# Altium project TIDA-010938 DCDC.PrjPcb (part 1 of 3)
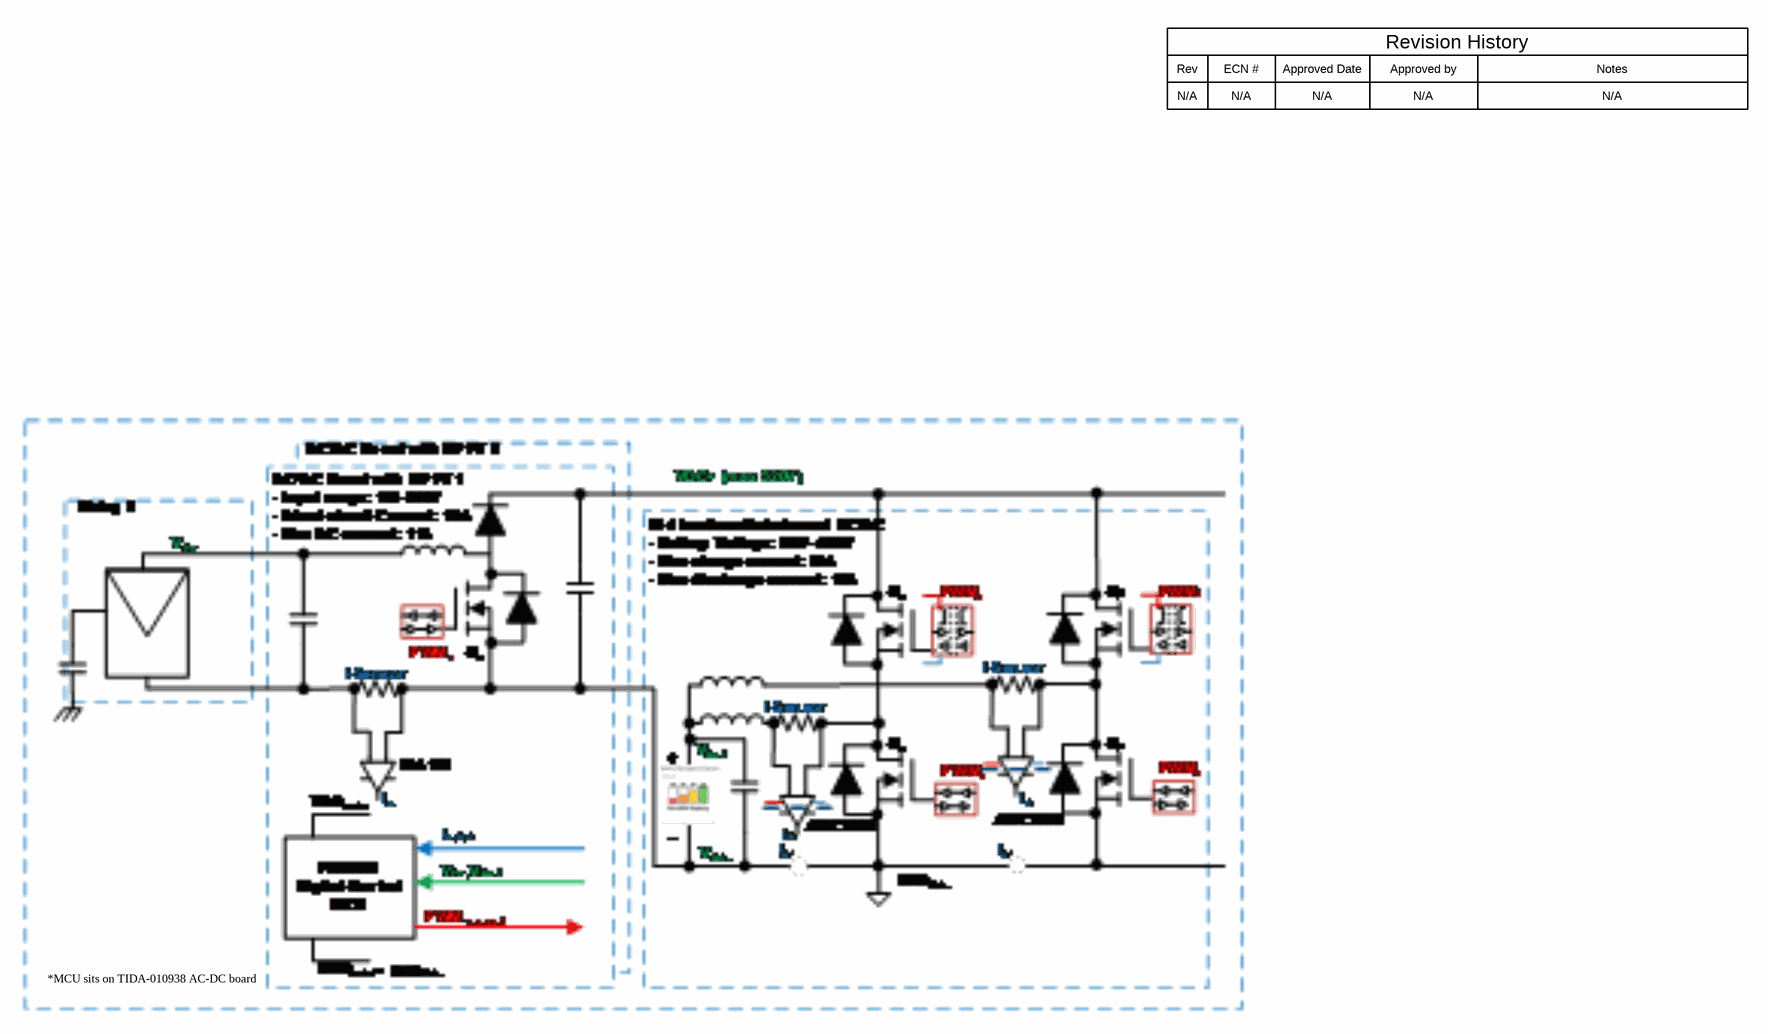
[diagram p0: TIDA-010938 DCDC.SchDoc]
CopyrightYear: 2023; PCB_Layout: Laure Chevallier; PCB_Rev: E1; PRJ_Customer: Public Release; PRJ_Engineer: Laure Chevallier; PRJ_Number: TIDA-010938 DC-DC; PRJ_Title: TIDA-010938 DC-DC; SCH_Rev: E1; TechSupport: http://www.ti.com/support; TID: A0497972
9 sheets, 437 parts. Net scope: flat (ports and power ports of the same name join across sheets).
Board file: TIDA-010938 DCDC.PcbDoc
Sheets:
  TIDA-010938 DCDC.SchDoc
    Designator = TIDA-010938 DCDC_Top.SchDoc
      Designator = TIDA-010938 DC-DC_Boost1.SchDoc
      Designator = TIDA-010938 DC-DC_Boost2.SchDoc
      Designator = TIDA-010938 bidirectional DC-DC_Interleaved1.SchDoc
      Designator = TIDA-010938 DC-DC_VoltageMeasurement.SchDoc
      Designator = TIDA-010938 DC-DC_Data conditionning.SchDoc
      Designator = TIDA-010938 bidirectional DC-DC_Interleaved2.SchDoc
      Designator = TIDA-010938 DCDC_Hardware.SchDoc

## Sheet TIDA-010938 DCDC.SchDoc
size 431 x 279 mm; Date: Not shown in title block; ApprovedBy: Not shown in title block; CheckedBy: Not shown in title block; Author: Not shown in title block; CompanyName: Not shown in title block; Engineer: Not shown in title block; Organization: Not shown in title block; Address1: Not shown in title block; Address2: Not shown in title block; Address3: Not shown in title block; Address4: Not shown in title block; DocumentNumber: 1; Revision: Use project parameter SCH_Rev; SheetNumber: 1; SheetTotal: 9; PageSetup: Record=PageOptions¦CenterHorizontal=True¦CenterVertical=True¦PrintScale=1.00¦XCorrection=1.00¦YCorrection=1.00¦PrintKind=0¦BorderSize=5000000¦LeftOffset=0¦BottomOffset=0¦Orientation=2¦PaperLength=1000¦PaperWidth=1000¦Scale=100¦PaperSource=15¦PrintQuality=600¦MediaType=1¦DitherType=10¦PaperKind=Letter¦PrintScaleMode=1

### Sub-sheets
Designator = TIDA-010938 DCDC_Top.SchDoc: no entries

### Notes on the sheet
- Rev
- N/A
- ECN #
- Approved Date
- Approved by
- Revision History
- Notes
- *MCU sits on TIDA-010938 AC-DC board

## Sheet TIDA-010938 DCDC_Top.SchDoc
size 431 x 279 mm; Date: Not shown in title block; ApprovedBy: Not shown in title block; CheckedBy: Not shown in title block; Author: Not shown in title block; CompanyName: Not shown in title block; Engineer: Not shown in title block; Organization: Not shown in title block; Address1: Not shown in title block; Address2: Not shown in title block; Address3: Not shown in title block; Address4: Not shown in title block; DocumentNumber: 1; Revision: Use project parameter SCH_Rev; SheetNumber: 2; SheetTotal: 9; PageSetup: Record=PageOptions¦CenterHorizontal=True¦CenterVertical=True¦PrintScale=1.00¦XCorrection=1.00¦YCorrection=1.00¦PrintKind=0¦BorderSize=5000000¦LeftOffset=0¦BottomOffset=0¦Orientation=2¦PaperLength=1000¦PaperWidth=1000¦Scale=100¦PaperSource=15¦PrintQuality=600¦MediaType=1¦DitherType=10¦PaperKind=Letter¦PrintScaleMode=1
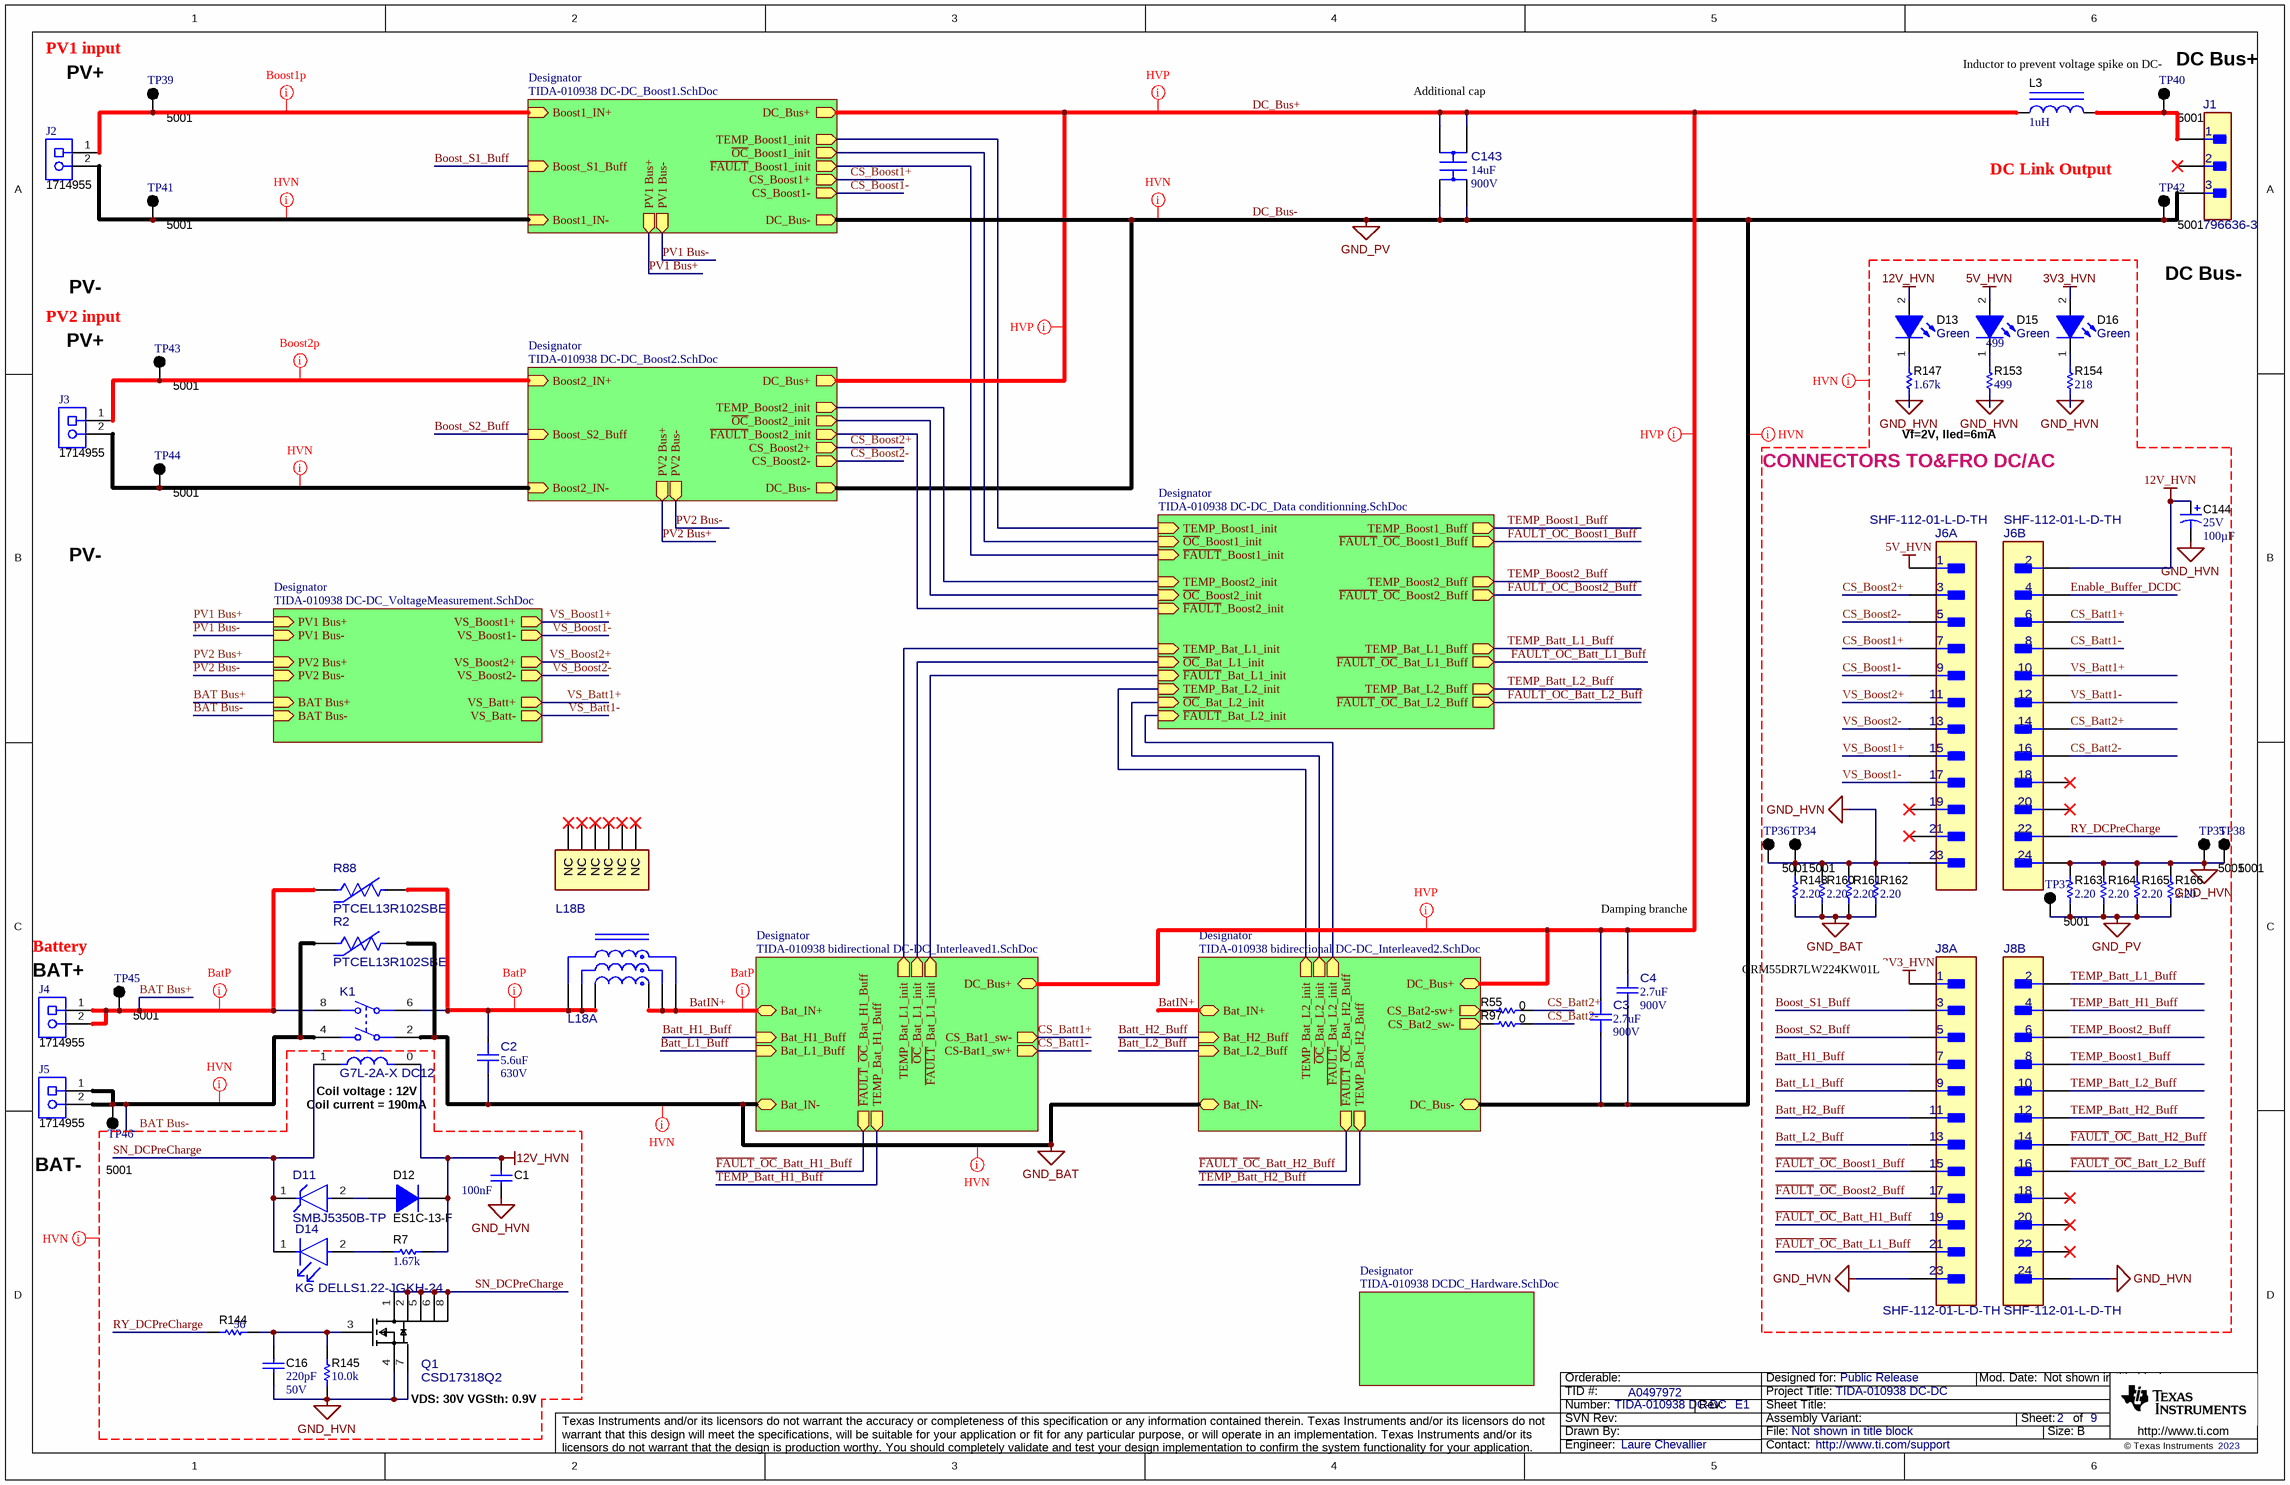
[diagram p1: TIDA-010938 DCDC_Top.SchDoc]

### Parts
C1  Cap_F: 100nF  [0603]  (hidden comment: GRM188R72A104KA35J)
C2  ValueDisplayed: 5.6uF  VDC_V: 630V  [FP-R533R456050P0M_RADIAL-MFG]  (hidden comment: R533R456050P0M)
C3  ValueDisplayed: 2.7uF  VDC_V: 900V  [FP-C4AKOBU4270A3YJ_RADIAL-MFG]  (hidden comment: C4AKOBU4270A3YJ)
C4  ValueDisplayed: 2.7uF  VDC_V: 900V  [FP-C4AKOBU4270A3YJ_RADIAL-MFG]  (hidden comment: C4AKOBU4270A3YJ)
C16  Cap_F: 220pF  VDC_V: 50V  [0603]  (hidden comment: GRM188R71H221KA01D)
C143  ValueDisplayed: 14uF  VDC_V: 900V  [FP-C4AKOBW5140A3JJ_RADIAL-MFG]  (hidden comment: C4AKOBW5140A3JJ)
C144  VDC_V: 25V  ValueDisplayed: 100µF  [UWT_630x770]  (hidden comment: UWT1E101MCL1GS)
D11  SMBJ5350B-TP  [FP-SMBJ5350B-TP_SMB-MFG]
D12  ES1C-13-F  [SMA]
D13  value Green  [WL-SMCW_GREEN]  (hidden comment: 150060VS75000)
D14  KG DELLS1.22-JGKH-24  [FP-KG DELLS1.22-JGKH-24_0603-MFG]
D15  value Green  [WL-SMCW_GREEN]  (hidden comment: 150060VS75000)
D16  value Green  [WL-SMCW_GREEN]  (hidden comment: 150060VS75000)
J1  796636-3  [FP-796636-3_HDR3-MFG]
J2  1714955  [Phoenix_1714955]
J3  1714955  [Phoenix_1714955]
J4  1714955  [Phoenix_1714955]
J5  1714955  [Phoenix_1714955]
J6  SHF-112-01-L-D-TH  [FP-SHF-112-01-L-D-TH_HDR24-MFG]  (parts A,B of 2)
J8  SHF-112-01-L-D-TH  [FP-SHF-112-01-L-D-TH_HDR24-MFG]  (parts A,B of 2)
K1  G7L-2A-X DC12  [FP-G7L-2A-X DC12_PTH_RELAY_52MM5_35MM5-MFG]
L3  ValueDisplayed: 1uH  [SRP1038A]  (hidden comment: SRP1038A-1R0M)
L18  B180986  [FP-B180986_PTH12-MFG]  (value not drawn)  (parts A,B of 2)
Q1  CSD17318Q2  [FP-CSD17318Q2_WSON6-MFG]
R2  PTCEL13R102SBE  [FP-PTCEL13R102SBE_RADIAL-MFG]
R7  ValueDisplayed: 1.67k  [0603]  (hidden comment: RT0603DRE071K67L)
R55  ValueDisplayed: 0  [0603]  (hidden comment: RCS06030000Z0EA)
R88  PTCEL13R102SBE  [FP-PTCEL13R102SBE_RADIAL-MFG]
R97  ValueDisplayed: 0  [0603]  (hidden comment: RCS06030000Z0EA)
R144  ValueDisplayed: 56  [0603]  (hidden comment: RG1608P-560-B-T5)
R145  ValueDisplayed: 10.0k  [0603]  (hidden comment: RG1608P-103-B-T5)
R147  ValueDisplayed: 1.67k  [0603]  (hidden comment: RT0603DRE071K67L)
R148  ValueDisplayed: 2.20  [1206]  (hidden comment: RC1206FR-072R2L)
R153  value 499  [0603]  (hidden comment: CRCW0603499RFKEAC)
R154  ValueDisplayed: 218  [0603]  (hidden comment: RT0603DRE07218RL)
R160  ValueDisplayed: 2.20  [1206]  (hidden comment: RC1206FR-072R2L)
R161  ValueDisplayed: 2.20  [1206]  (hidden comment: RC1206FR-072R2L)
R162  ValueDisplayed: 2.20  [1206]  (hidden comment: RC1206FR-072R2L)
R163  ValueDisplayed: 2.20  [1206]  (hidden comment: RC1206FR-072R2L)
R164  ValueDisplayed: 2.20  [1206]  (hidden comment: RC1206FR-072R2L)
R165  ValueDisplayed: 2.20  [1206]  (hidden comment: RC1206FR-072R2L)
R166  ValueDisplayed: 2.20  [1206]  (hidden comment: RC1206FR-072R2L)
TP34  5001  [Keystone5001]
TP35  5001  [Keystone5001]
TP36  5001  [Keystone5001]
TP37  5001  [Keystone5001]
TP38  5001  [Keystone5001]
TP39  5001  [Keystone5001]
TP40  5001  [Keystone5001]
TP41  5001  [Keystone5001]
TP42  5001  [Keystone5001]
TP43  5001  [Keystone5001]
TP44  5001  [Keystone5001]
TP45  5001  [Keystone5001]
TP46  5001  [Keystone5001]

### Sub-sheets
Designator = TIDA-010938 DC-DC_Boost1.SchDoc: Boost_S1_Buff (in), TEMP_Boost1_init (out), ~{FAULT}_Boost1_init (out), ~{OC}_Boost1_init (out), DC_Bus+ (out), DC_Bus- (out), Boost1_IN+ (in), Boost1_IN- (in), CS_Boost1+ (out), CS_Boost1- (out), PV1 Bus+ (out), PV1 Bus- (out)
Designator = TIDA-010938 DC-DC_Boost2.SchDoc: DC_Bus+ (out), DC_Bus- (out), Boost_S2_Buff (in), TEMP_Boost2_init (out), ~{FAULT}_Boost2_init (out), ~{OC}_Boost2_init (out), Boost2_IN+ (in), Boost2_IN- (in), CS_Boost2+ (out), CS_Boost2- (out), PV2 Bus+ (out), PV2 Bus- (out)
Designator = TIDA-010938 bidirectional DC-DC_Interleaved1.SchDoc: DC_Bus+ (bidir), Bat_IN+ (bidir), Bat_IN- (bidir), Bat_L1_Buff (in), Bat_H1_Buff (in), ~{FAULT}_Bat_L1_init (out), ~{FAULT}_~{OC}_Bat_H1_Buff (out), ~{OC}_Bat_L1_init (out), TEMP_Bat_H1_Buff (out), TEMP_Bat_L1_init (out), CS_Bat1_sw- (out), CS-Bat1_sw+ (out)
Designator = TIDA-010938 DC-DC_VoltageMeasurement.SchDoc: PV1 Bus+ (in), PV2 Bus+ (in), VS_Boost2+ (out), BAT Bus+ (in), BAT Bus- (in), VS_Batt+ (out), VS_Boost1+ (out), VS_Batt- (out), VS_Boost2- (out), VS_Boost1- (out), PV2 Bus- (in), PV1 Bus- (in)
Designator = TIDA-010938 DC-DC_Data conditionning.SchDoc: ~{FAULT}_Boost1_init (in), ~{OC}_Boost1_init (in), ~{FAULT}_Boost2_init (in), ~{OC}_Boost2_init (in), ~{FAULT}_Bat_L1_init (in), ~{OC}_Bat_L1_init (in), ~{FAULT}_Bat_L2_init (in), ~{OC}_Bat_L2_init (in), TEMP_Boost1_init (in), TEMP_Boost2_init (in), TEMP_Bat_L1_init (in), TEMP_Bat_L2_init (in), TEMP_Boost1_Buff (out), ~{FAULT}_~{OC}_Boost1_Buff (out), TEMP_Boost2_Buff (out), ~{FAULT}_~{OC}_Boost2_Buff (out), TEMP_Bat_L1_Buff (out), ~{FAULT}_~{OC}_Bat_L1_Buff (out), TEMP_Bat_L2_Buff (out), ~{FAULT}_~{OC}_Bat_L2_Buff (out)
Designator = TIDA-010938 bidirectional DC-DC_Interleaved2.SchDoc: DC_Bus+ (bidir), DC_Bus- (bidir), Bat_IN+ (bidir), Bat_IN- (bidir), Bat_L2_Buff (in), Bat_H2_Buff (in), TEMP_Bat_H2_Buff (out), ~{FAULT}_~{OC}_Bat_H2_Buff (out), ~{FAULT}_Bat_L2_init (out), ~{OC}_Bat_L2_init (out), TEMP_Bat_L2_init (out), CS_Bat2-sw+ (out), CS_Bat2_sw- (out)
Designator = TIDA-010938 DCDC_Hardware.SchDoc: no entries

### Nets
3V3_HVN: D16.2(A) J8.1
5V_HVN: D15.2(A) J6.1
12V_HVN: C1.1 C144.1(+) D12.1(K) D13.2(A) J6.2 K1.0 R7.1
DC_Bus-: C3.2 C4.2 C143.2 C143.4 J1.3 R163.1 R164.1 R165.1 R166.1 TP37.1 TP42.1 ; sheet Designator/DC_Bus-, sheet Designator/DC_Bus-, sheet Designator/DC_Bus-  [also labelled GND_PV]
GND_BAT: C2.1 K1.2 R2.2 R148.1 R160.1 R161.1 R162.1 ; sheet Designator/Bat_IN-, sheet Designator/Bat_IN-
GND_HVN: C1.2 C16.1 C144.2(-) J6.23 J6.24 J8.23 J8.24 Q1.4(S) Q1.7(S) R145.2 R147.1 R148.2 R153.1 R154.1 R160.2 R161.2 R162.2 R163.2 R164.2 R165.2 R166.2 TP34.1 TP35.1 TP36.1 TP38.1
BAT Bus+: J4.1 J4.2 K1.8 R88.1 TP45.1 ; sheet Designator/BAT Bus+
BAT Bus-: J5.1 J5.2 K1.4 R2.1 TP46.1 ; sheet Designator/BAT Bus-
BatIN+: L18.1 L18.2 L18.3 ; sheet Designator/Bat_IN+, sheet Designator/Bat_IN+
Batt_H1_Buff: J8.7 ; sheet Designator/Bat_H1_Buff
Batt_H2_Buff: J8.11 ; sheet Designator/Bat_H2_Buff
Batt_L1_Buff: J8.9 ; sheet Designator/Bat_L1_Buff
Batt_L2_Buff: J8.13 ; sheet Designator/Bat_L2_Buff
Boost_S1_Buff: J8.3 ; sheet Designator/Boost_S1_Buff
Boost_S2_Buff: J8.5 ; sheet Designator/Boost_S2_Buff
CS_Batt1+: J6.6 ; sheet Designator/CS_Bat1_sw-
CS_Batt1-: J6.8 ; sheet Designator/CS-Bat1_sw+
CS_Batt2+: J6.14 R55.2
CS_Batt2-: J6.16 R97.2
CS_Boost1+: J6.7 ; sheet Designator/CS_Boost1+
CS_Boost1-: J6.9 ; sheet Designator/CS_Boost1-
CS_Boost2+: J6.3 ; sheet Designator/CS_Boost2+
CS_Boost2-: J6.5 ; sheet Designator/CS_Boost2-
DC_Bus+: C3.1 C4.1 C143.1 C143.3 L3.1 ; sheet Designator/DC_Bus+, sheet Designator/DC_Bus+, sheet Designator/DC_Bus+, sheet Designator/DC_Bus+
Enable_Buffer_DCDC: J6.4
~{FAULT}_~{OC}_Batt_H1_Buff: J8.19 ; sheet Designator/~{FAULT}_~{OC}_Bat_H1_Buff
~{FAULT}_~{OC}_Batt_H2_Buff: J8.14 ; sheet Designator/~{FAULT}_~{OC}_Bat_H2_Buff
~{FAULT}_~{OC}_Batt_L1_Buff: J8.21 ; sheet Designator/~{FAULT}_~{OC}_Bat_L1_Buff
~{FAULT}_~{OC}_Batt_L2_Buff: J8.16 ; sheet Designator/~{FAULT}_~{OC}_Bat_L2_Buff
~{FAULT}_~{OC}_Boost1_Buff: J8.15 ; sheet Designator/~{FAULT}_~{OC}_Boost1_Buff
~{FAULT}_~{OC}_Boost2_Buff: J8.17 ; sheet Designator/~{FAULT}_~{OC}_Boost2_Buff
PV1 Bus+: sheet Designator/PV1 Bus+, sheet Designator/PV1 Bus+
PV1 Bus-: sheet Designator/PV1 Bus-, sheet Designator/PV1 Bus-
PV2 Bus+: sheet Designator/PV2 Bus+, sheet Designator/PV2 Bus+
PV2 Bus-: sheet Designator/PV2 Bus-, sheet Designator/PV2 Bus-
RY_DCPreCharge: J6.22 R144.1
SN_DCPreCharge: D11.1(CATHODE) D14.1(CATHODE) K1.1 Q1.1(D) Q1.2(D) Q1.5(D) Q1.6(D) Q1.8(D)
TEMP_Batt_H1_Buff: J8.4 ; sheet Designator/TEMP_Bat_H1_Buff
TEMP_Batt_H2_Buff: J8.12 ; sheet Designator/TEMP_Bat_H2_Buff
TEMP_Batt_L1_Buff: J8.2 ; sheet Designator/TEMP_Bat_L1_Buff
TEMP_Batt_L2_Buff: J8.10 ; sheet Designator/TEMP_Bat_L2_Buff
TEMP_Boost1_Buff: J8.8 ; sheet Designator/TEMP_Boost1_Buff
TEMP_Boost2_Buff: J8.6 ; sheet Designator/TEMP_Boost2_Buff
VS_Batt1+: J6.10 ; sheet Designator/VS_Batt+
VS_Batt1-: J6.12 ; sheet Designator/VS_Batt-
VS_Boost1+: J6.15 ; sheet Designator/VS_Boost1+
VS_Boost1-: J6.17 ; sheet Designator/VS_Boost1-
VS_Boost2+: J6.11 ; sheet Designator/VS_Boost2+
VS_Boost2-: J6.13 ; sheet Designator/VS_Boost2-
NetC2_2: C2.2 K1.6 L18.4 L18.5 L18.6 R88.2
NetC16_2: C16.2 Q1.3(G) R144.2 R145.1
NetD11_2: D11.2(ANODE) D12.2(A)
NetD13_1: D13.1(K) R147.2
NetD14_2: D14.2(ANODE) R7.2
NetD15_1: D15.1(K) R153.2
NetD16_1: D16.1(K) R154.2
NetJ1_1: J1.1 L3.2 TP40.1
NetJ2_1: J2.1 TP39.1 ; sheet Designator/Boost1_IN+
NetJ2_2: J2.2 TP41.1 ; sheet Designator/Boost1_IN-
NetJ3_1: J3.1 TP43.1 ; sheet Designator/Boost2_IN+
NetJ3_2: J3.2 TP44.1 ; sheet Designator/Boost2_IN-
NetR55_1: R55.1 ; sheet Designator/CS_Bat2-sw+
NetR97_1: R97.1 ; sheet Designator/CS_Bat2_sw-
(unnamed): sheet Designator/TEMP_Boost1_init, sheet Designator/TEMP_Boost1_init
(unnamed): sheet Designator/~{FAULT}_Boost1_init, sheet Designator/~{FAULT}_Boost1_init  [a separate net that carries the same name]
(unnamed): sheet Designator/~{OC}_Boost1_init, sheet Designator/~{OC}_Boost1_init  [a separate net that carries the same name]
(unnamed): sheet Designator/TEMP_Boost2_init, sheet Designator/TEMP_Boost2_init  [a separate net that carries the same name]
(unnamed): sheet Designator/~{FAULT}_Boost2_init, sheet Designator/~{FAULT}_Boost2_init  [a separate net that carries the same name]
(unnamed): sheet Designator/~{OC}_Boost2_init, sheet Designator/~{OC}_Boost2_init  [a separate net that carries the same name]
(unnamed): sheet Designator/~{FAULT}_Bat_L1_init, sheet Designator/~{FAULT}_Bat_L1_init  [a separate net that carries the same name]
(unnamed): sheet Designator/~{OC}_Bat_L1_init, sheet Designator/~{OC}_Bat_L1_init  [a separate net that carries the same name]
(unnamed): sheet Designator/TEMP_Bat_L1_init, sheet Designator/TEMP_Bat_L1_init  [a separate net that carries the same name]
(unnamed): sheet Designator/~{FAULT}_Bat_L2_init, sheet Designator/~{FAULT}_Bat_L2_init  [a separate net that carries the same name]
(unnamed): sheet Designator/~{OC}_Bat_L2_init, sheet Designator/~{OC}_Bat_L2_init  [a separate net that carries the same name]
(unnamed): sheet Designator/TEMP_Bat_L2_init, sheet Designator/TEMP_Bat_L2_init  [a separate net that carries the same name]

Not connected (* = marked no-connect by the designer): J1 2*; J6 18* 19* 20* 21*; J8 18* 20* 22*; L18 7(NC)* 8(NC)* 9(NC)* 10(NC)* 11(NC)* 12(NC)*

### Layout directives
net class HVN: 3V3_HVN, 5V_HVN, 12V_HVN, BAT Bus-, Batt_H1_Buff, Batt_H2_Buff, Batt_L1_Buff, Batt_L2_Buff, Boost_S1_Buff, Boost_S2_Buff, CS_Batt1+, CS_Batt1-, CS_Batt2+, CS_Batt2-, CS_Boost1+, CS_Boost1-, CS_Boost2+, CS_Boost2-, DC_Bus-, Enable_Buffer_DCDC, GND_BAT, GND_HVN, GND_PV, NetJ2_2, NetJ3_2, RY_DCPreCharge, SN_DCPreCharge, TEMP_Batt_H1_Buff, TEMP_Batt_H2_Buff, TEMP_Batt_L1_Buff, TEMP_Batt_L2_Buff, TEMP_Boost1_Buff, TEMP_Boost2_Buff, VS_Batt1+, VS_Batt1-, VS_Boost1+, VS_Boost1-, VS_Boost2+, VS_Boost2-, ~{FAULT}_~{OC}_Batt_H1_Buff, ~{FAULT}_~{OC}_Batt_H2_Buff, ~{FAULT}_~{OC}_Batt_L1_Buff, ~{FAULT}_~{OC}_Batt_L2_Buff, ~{FAULT}_~{OC}_Boost1_Buff, ~{FAULT}_~{OC}_Boost2_Buff
net class Boost1p: NetJ2_1
net class Boost2p: NetJ3_1
net class HVP: DC_Bus+
net class BatP: BAT Bus+, BatIN+, NetC2_2

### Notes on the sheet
- (near TP39) PV1 input
- PV+
- Additional cap
- Inductor to prevent voltage spike on DC-
- (near TP40) DC Bus+
- DC Link Output
- PV-
- DC Bus-
- PV2 input
- Vf=2V, Iled=6mA
- CONNECTORS TO&FRO DC/AC
- Battery
- BAT+
- Damping branche
- GRM55DR7LW224KW01L
- (near K1) Coil voltage : 12V
- (near K1) Coil current = 190mA
- BAT-
- (near Q1) VDS: 30V VGSth: 0.9V

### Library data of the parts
C1 = CMP-0007470-5: CAP, CERM, 0.1 uF, 100 V, +/- 10%, X7R, 0603; Manufacturer: MuRata; TaMin_C: -55°C; Polarized: N; SizeAreaWB_mm2: 4.68; Value1: Unknown; U/M: EA; Value: 0.1uF; TaMax_C: 125°C; SizeZ_mm: 1; SizeX_mm: 1.6; SizeY_mm: 0.8; Value2: 100V; SizeArea_mm2: 1.28; AEC Category: Q200
C2 = CMP-0045188-1: 5.6 µF Film Capacitor 310V 630V Polypropylene (PP), Metallized Radial; Manufacturer: KEMET; AEC Grade: Grade 3; AEC Qualified: Yes; Cap_F: 5.6µF; SizeZ_mm: 30.3mm; Tolerance_%: 20%; VAC_X: X2; Value: 5.6µF
C3 C4 = CMP-0045062-1: 2.7 µF Film Capacitor 900V Polypropylene (PP), Metallized Radial; Manufacturer: Kemet; AEC Grade: Grade 1; AEC Qualified: Yes; Cap_F: 2.7µF; SizeZ_mm: 28.7mm; Tolerance_%: 5%; Value: 2.7µF
C16 = CMP-0007442-5: CAP, CERM, 220 pF, 50 V, +/- 10%, X7R, 0603; Manufacturer: MuRata; TaMin_C: -55°C; Polarized: N; SizeAreaWB_mm2: 4.68; Value1: Unknown; U/M: EA; Value: 220pF; TaMax_C: 125°C; SizeZ_mm: 1; SizeX_mm: 1.6; SizeY_mm: 0.8; SizeArea_mm2: 1.28; AEC Category: Q200
C143 = CMP-0045770-1: 14 µF Film Capacitor 900V Polypropylene (PP), Metallized Radial - 4 Leads; Manufacturer: Kemet; AEC Grade: Grade 1; AEC Qualified: Yes; Cap_F: 14µF; SizeZ_mm: 38mm; Tolerance_%: 5%; Standoff Height: 0.5mm; Value: 14µF
C144 = CMP-0081462-1: CAP, AL, 100 µF, 25 V, +/- 20%, SMD; Manufacturer: Nichicon; TaMin_C: -55°C; Polarized: Y; SizeAreaWB_mm2: 77.4; U/M: EA; Value: 100uF; TaMax_C: 105°C; SizeZ_mm: 8; SizeX_mm: 7; SizeY_mm: 6.6; Cap_Case: 6.3x7.7mm; SizeArea_mm2: 46.2; CompType: Capacitor; AEC Qualified: N; IRMS_A: 91mA; AEC Category: Q200
D11 = CMP-0097215-1: Zener Diode 13 V 5 W ±5% Surface Mount DO-214AA (SMB); Manufacturer: MCC; Power_W: 5W; Standoff Height: 0.05mm; Vr_V: 9.9V; SizeZ_mm: 2.62mm; Zener Impedance: 2.5Ω; AEC Qualified: No; Max Reverse Leakage Current: 1uA; Vz_V: 13V; Vf_V: 13.65V; TJmax_C: 150°C
D12 = CMP-0029023-2: Diode, Superfast Rectifier, 150 V, 1 A, SMA; Manufacturer: Diodes Inc.; TJmax_C: 150°C; Vr_V: 150V; Value2: 0.92V; SizeX_mm: 5.59; Green_REACh: Incomplete; SizeAreaWB_mm2: 37.3428; Value: 150V; Vf_V: 920mV; Green_Lifecycle: Not Set; Value1: 1A; SizeZ_mm: 2.87; SizeArea_mm2: 16.3228; SizeY_mm: 2.92; AEC Category: Q101; RJC_CperW: 25
D13 D15 D16 = CMP-0002894-2: LED, Green, SMD; Manufacturer: Wurth Elektronik; Type: AlInGaP; Value2: 2V; Io_A: 20mA; Value1: W
D14 = CMP-0093310-1: Standard LEDs - SMD Green TOPLED E 1608; Manufacturer: Osram Opto; AEC Grade: Grade 2; LambdaP: 572nm; SizeZ_mm: 0.7mm; LuminousFlux_PhiV: 0.016-0.0295lm; Luminous Intensity: 4.5-9.7mcd; LambdaD: 570nm; Tjmax_C: 125°C; Angle: 120°; Led Orientation: Top View; Forward Current: 2mA; Vf_V: 1.8V; AEC Qualified: Yes; Vr_V: 12V
J1 = CMP-0094328-1: 3 Position Terminal Block Header, Male Pins, Shrouded (4 Side) 0.200" (5.08mm) Vertical - Through Hole; Manufacturer: TE Connectivity; Current_A: 15A; Row_Count: 1; AEC Qualified: No; Voltage_V: 300V; SizeZ_mm: 12.25mm; Min Wire Gauge: 30; ContactFinish: Tin; Max Wire Gauge: 12
J2-J5 = CMP-0055505-1: Terminal Block, 2x1, 6.35mm, Green, TH; Manufacturer: Phoenix Contact; CNHeader: FALSE; Shrouded: Y; Gender: Female; Row_Count: 1; Pitch_mm: 6.35; CT: TRUE
J6 J8 = CMP-0003796-1: Conn Shrouded Header (4 Sides) HDR 24 POS 1.27mm Solder ST Top Entry Thru-Hole Tube; Manufacturer: Samtec; ContactFinish: Gold,Nickel; Row_Count: 2; AEC Qualified: No; Conn Gender: Male; Conn Orientation: Straight; SizeZ_mm: 5.46mm; Standoff Height: 0.38mm
K1 = CMP-0093885-1: General Purpose Relay DPST-NO (2 Form A) 12VDC Coil Through Hole; Manufacturer: Omron; SizeZ_mm: 41mm; Coil Power_W: 2.3W; TaMax_C: +85°C; Switching Current: 30A; TaMin_C: -40°C; Coil Voltage_VDC: 12V; Coil Current_A: 191.7mA; Coil Resistance: 63Ω; Coil Type: Non-Latching; AEC Qualified: No
L3 = CMP-0056795-1: Inductor, Shielded, Powdered Iron, 1 uH, 18 A, 0.003 ohm, AEC-Q200 Grade 1, SMD; Manufacturer: Bourns; Isat: 36A @ 20% inductance drop; Irms: 18A @ 40C rise; Green_Lifecycle: Active; SizeAreaWB_mm2: 156; DCR_ohm: 3m; Green_REACh: Passed; Value: 1uH; Imax_A: 18A; SizeZ_mm: 4; SizeX_mm: 11; SizeY_mm: 10; SizeArea_mm2: 110; Ind_H: 1µH; AEC Qualified: Y; AEC Grade: 1; AEC Category: Q200
L18 = CMP-0047896-1: Inductor 22μH 4.7mΩ; Manufacturer: Bourns; AEC Qualified: No; DCR_ohm: 4.7m; SizeZ_mm: 40mm; Value: 22uH; Test Frequency: 100kHz
Q1 = CMP-0076725-1: 30-V N-Channel NexFET™ Power MOSFET; Manufacturer: Texas Instruments; VdsMax_V: 30V; SizeZ_mm: 0.8mm; ChMode: False; QgTyp_nC: 6nC @ 4.5V; Rdson45_ohm: 0.0139; Vgs_V: 10V; AEC Qualified: No; IdsMax_A: 10A
R2 R88 = CMP-0043438-1: PTCEL Series 850 V 1 kOhm ±30 % Radial Inrush Current Limiter PTC Thermistor; Manufacturer: Vishay; SizeZ_mm: 17mm; Value: 1000Ω; AEC Grade: Grade 2; AEC Qualified: Yes; Hold Current: 30mA; Max Current: 40A; Standoff Height: 2mm; Tolerance_%: 30%; VDC_V: 850V
R7 R147 = CMP-0024836-3: RES, 1.67 k, 0.5%, 0.1 W, 0603; Manufacturer: Yageo America; Power_W: 100mW; TempCo: 50 ppm/C; Value_Code: 1k67; U/M: EA; Value: 1.67k; EIA_Code: E192; SizeX_mm: 1.6; SizeY_mm: 0.8; SizeZ_mm: 1; Value2: 0.1W; SizeArea_mm2: 1.28; VDC_V: 75V; AEC Category: Q200
R55 R97 = CMP-0081973-1: RES, 0, 0%, 0.25 W, AEC-Q200 Grade 0, 0603; Manufacturer: Vishay-Dale; SizeAreaWB_mm2: 4.68; SizeArea_mm2: 1.28; AEC Qualified: Y; AEC Category: Q200; Value: 0; SizeZ_mm: 1; SizeY_mm: 0.8; Power_W: 250mW; Value2: 0.25W; SizeX_mm: 1.6
R144 = CMP-0023572-3: RES, 56, 0.1%, 0.1 W, 0603; Manufacturer: Susumu Co Ltd; Power_W: 100mW; TempCo: 25 ppm/C; Value_Code: 56R0; U/M: EA; Value: 56; SizeX_mm: 1.6; SizeY_mm: 0.8; SizeZ_mm: 1; Value2: 0.1W; SizeArea_mm2: 1.28; VDC_V: 75V; AEC Category: Q200
R145 = CMP-0023404-1: RES, 10.0 k, 0.1%, 0.1 W, 0603; Manufacturer: Susumu Co Ltd; Power_W: 100mW; TempCo: 25 ppm/C; Value_Code: 10k0; U/M: EA; Value: 10.0k; EIA_Code: E192; Res_ohm: 10k; SizeX_mm: 1.6; SizeY_mm: 0.8; SizeZ_mm: 1; Value2: 0.1W; SizeArea_mm2: 1.28; VDC_V: 75V; AEC Category: Q200
R148 R160-R166 = CMP-0018170-2: RES, 2.20, 1%, 0.25 W, 1206; Manufacturer: Yageo America; Power_W: 250mW; TempCo: 200 ppm/C; Value_Code: 2R20; U/M: EA; Value: 2.20; Res_ohm: 2.2; SizeX_mm: 3.2; SizeY_mm: 1.6; SizeZ_mm: 1.35; Value2: 0.25W; SizeArea_mm2: 5.12; VDC_V: 200V; AEC Category: Q200
R153 = CMP-0082532-1: RES, 499, 1%, 0.1 W, 0603; Manufacturer: Vishay-Dale; Power_W: 100mW; TempCo: 100 ppm/C; SizeAreaWB_mm2: 4.68; Value_Code: 499R; EIA_Code: E96; SizeX_mm: 1.6; SizeY_mm: 0.8; SizeZ_mm: 1; Value2: 0.1W; SizeArea_mm2: 1.28; AEC Qualified: N; VDC_V: 75V; AEC Category: Q200
R154 = CMP-0024934-2: RES, 218, 0.5%, 0.1 W, 0603; Manufacturer: Yageo America; Power_W: 100mW; TempCo: 50 ppm/C; Value_Code: 218R; U/M: EA; Value: 218; EIA_Code: E192; SizeX_mm: 1.6; SizeY_mm: 0.8; SizeZ_mm: 1; Value2: 0.1W; SizeArea_mm2: 1.28; VDC_V: 75V; AEC Category: Q200
TP34-TP46 = CMP-0055138-2: Test Point, Miniature, Black, TH; Manufacturer: Keystone Electronics; ContactFinish: Silver; CNHeader: FALSE; Green_Lifecycle: Active; Green_REACh: Passed; CT: TRUE

## Sheet TIDA-010938 DC-DC_Boost1.SchDoc
size 431 x 279 mm; Date: Not shown in title block; ApprovedBy: Not shown in title block; CheckedBy: Not shown in title block; Author: Not shown in title block; CompanyName: Not shown in title block; Engineer: Not shown in title block; Organization: Not shown in title block; Address1: Not shown in title block; Address2: Not shown in title block; Address3: Not shown in title block; Address4: Not shown in title block; DocumentNumber: 1; Revision: Use project parameter SCH_Rev; SheetNumber: 3; SheetTotal: 9; PageSetup: Record=PageOptions¦CenterHorizontal=True¦CenterVertical=True¦PrintScale=1.00¦XCorrection=1.00¦YCorrection=1.00¦PrintKind=0¦BorderSize=5000000¦LeftOffset=0¦BottomOffset=0¦Orientation=2¦PaperLength=1000¦PaperWidth=1000¦Scale=100¦PaperSource=15¦PrintQuality=600¦MediaType=1¦DitherType=10¦PaperKind=Letter¦PrintScaleMode=1
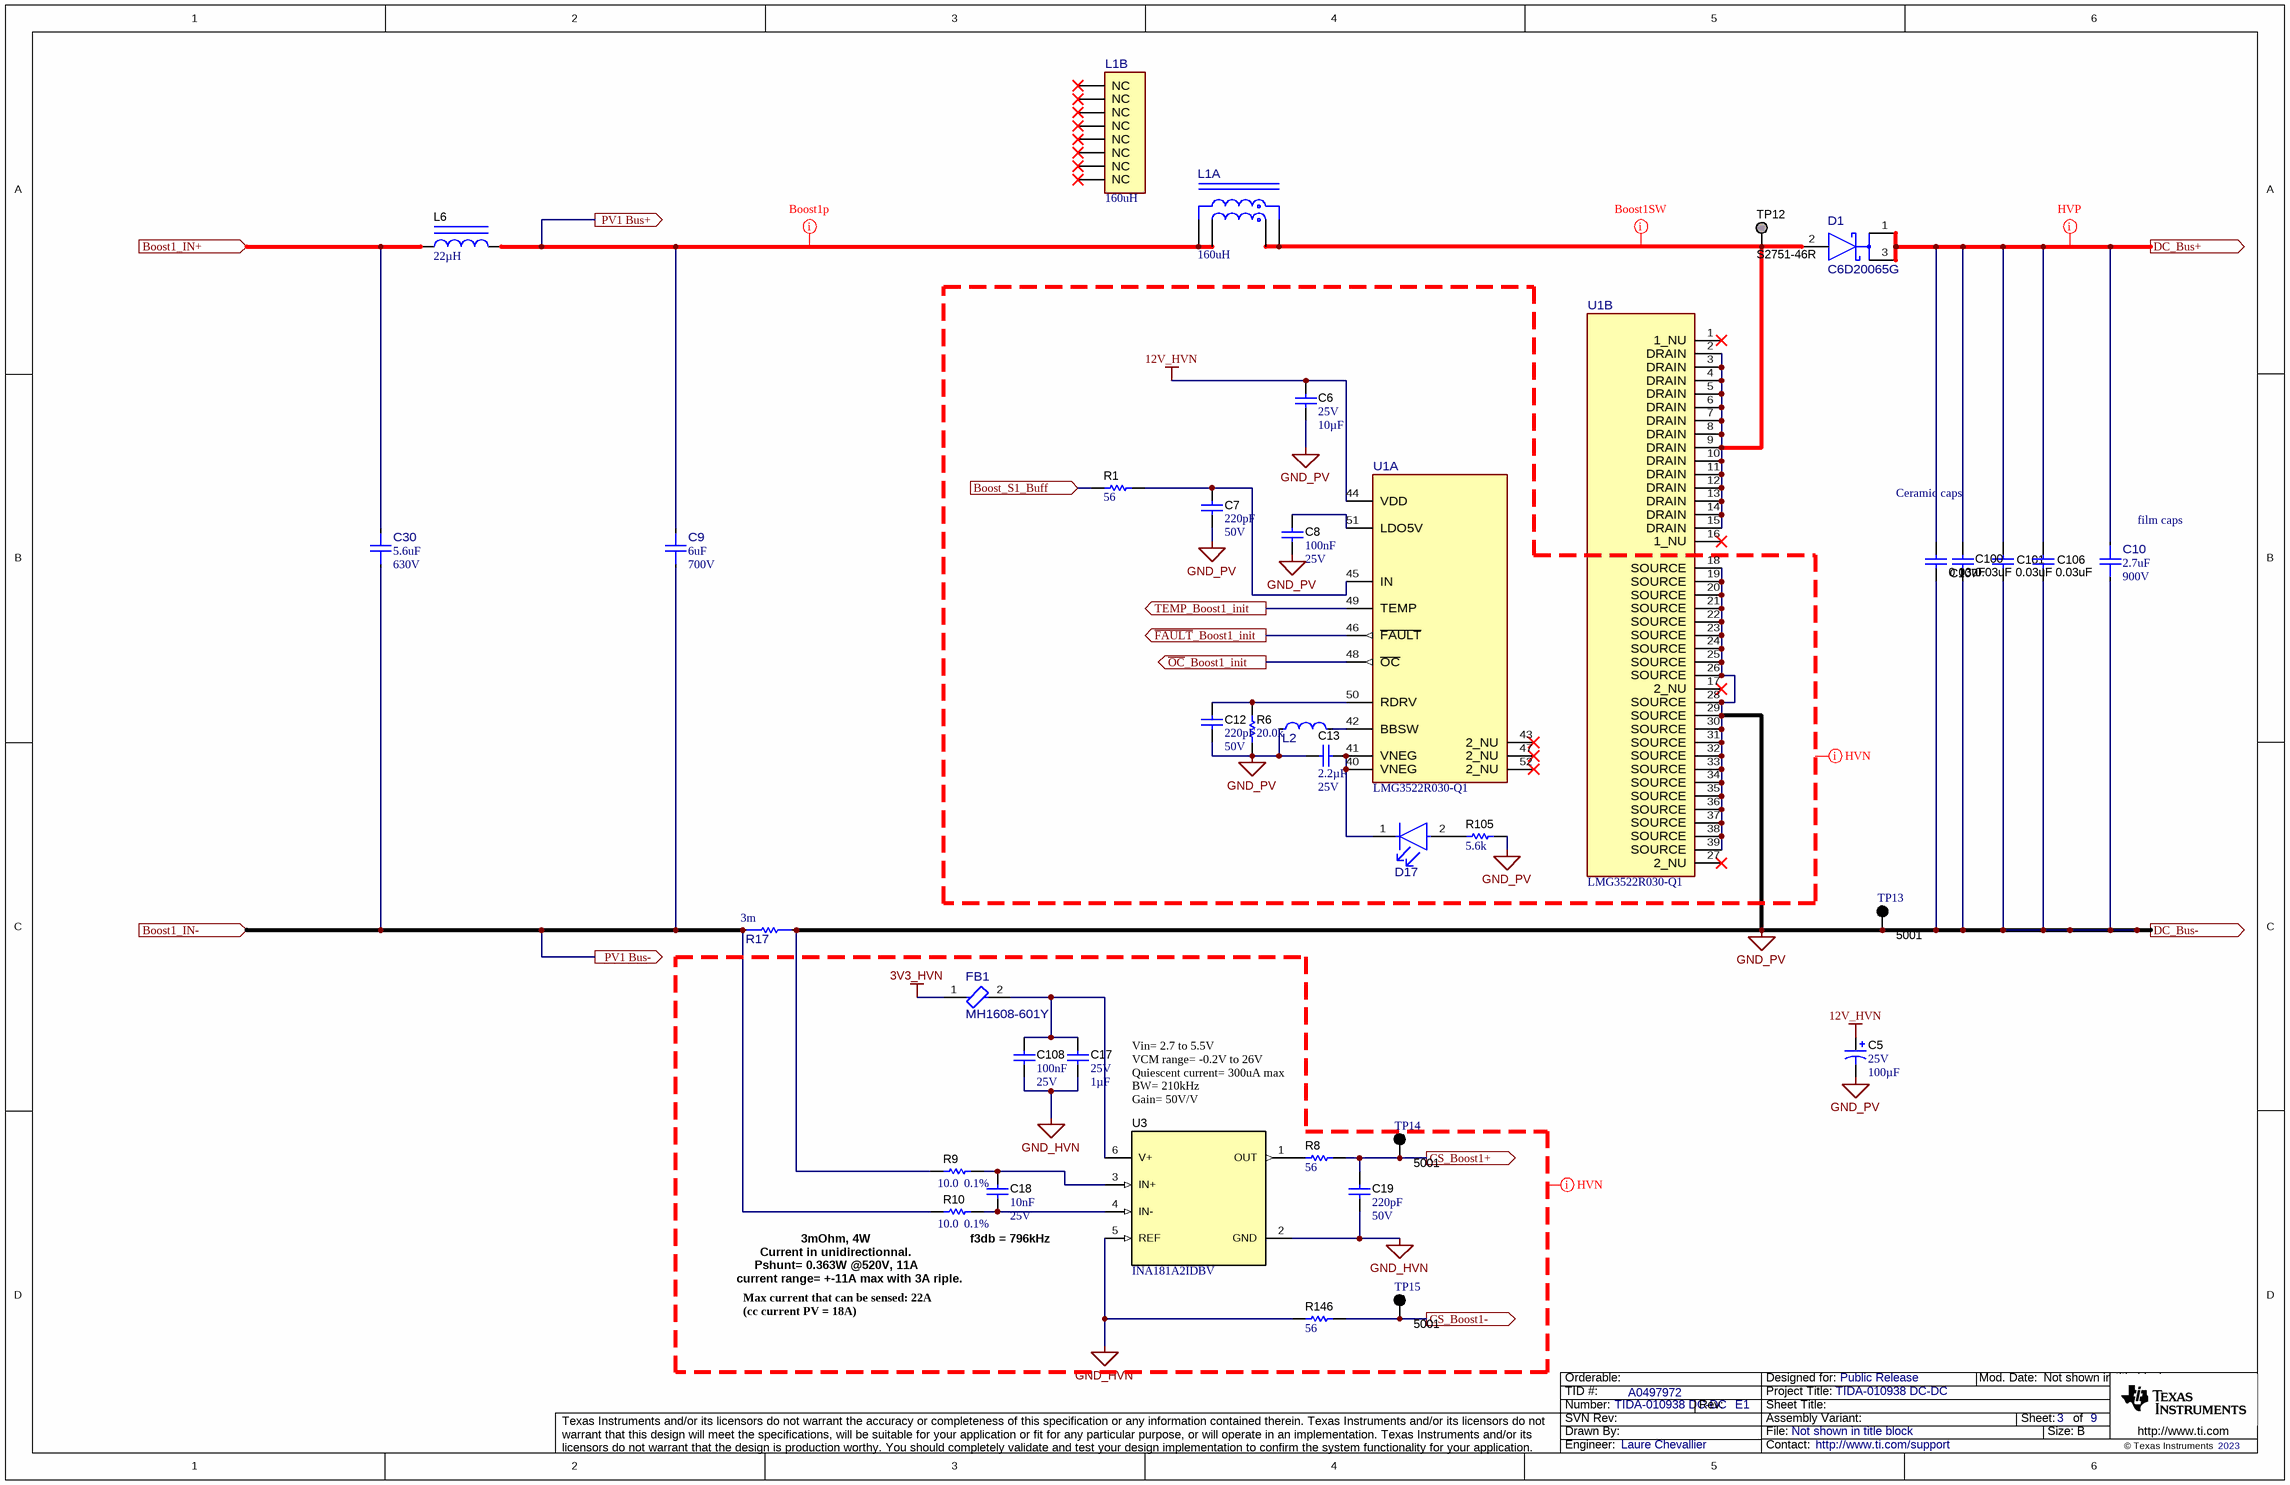
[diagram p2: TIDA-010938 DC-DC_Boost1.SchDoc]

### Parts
C5  VDC_V: 25V  ValueDisplayed: 100µF  [UWT_630x770]  (hidden comment: UWT1E101MCL1GS)
C6  VDC_V: 25V  ValueDisplayed: 10µF  [1206_180]  (hidden comment: TMK316AB7106KLHT)
C7  Cap_F: 220pF  VDC_V: 50V  [0603]  (hidden comment: GRM188R71H221KA01D)
C8  Cap_F: 100nF  VDC_V: 25V  [0603]  (hidden comment: 06033C104JAT2A)
C9  ValueDisplayed: 6uF  VDC_V: 700V  [FP-C4AUJBU4600M18J_RADIAL-MFG]  (hidden comment: C4AUJBU4600M18J)
C10  ValueDisplayed: 2.7uF  VDC_V: 900V  [FP-C4AKOBU4270A3YJ_RADIAL-MFG]  (hidden comment: C4AKOBU4270A3YJ)
C12  Cap_F: 220pF  VDC_V: 50V  [0603]  (hidden comment: GRM188R71H221KA01D)
C13  Cap_F: 2.2µF  VDC_V: 25V  [0805_HV]  (hidden comment: CGA4J3X7R1E225K125AB)
C17  VDC_V: 25V  ValueDisplayed: 1µF  [0603]  (hidden comment: TMK107BJ105KA-T)
C18  Cap_F: 10nF  VDC_V: 25V  [0603]  (hidden comment: SR0603X7R103K1NT95(F)#M123A)
C19  Cap_F: 220pF  VDC_V: 50V  [0603]  (hidden comment: GRM188R71H221KA01D)
C30  ValueDisplayed: 5.6uF  VDC_V: 630V  [FP-R533R456050P0M_RADIAL-MFG]  (hidden comment: R533R456050P0M)
C100  ValueDisplayed: 0.03uF  [1812_254]  (hidden comment: C1812C303KDGLCAUTO)
C101  ValueDisplayed: 0.03uF  [1812_254]  (hidden comment: C1812C303KDGLCAUTO)
C106  ValueDisplayed: 0.03uF  [1812_254]  (hidden comment: C1812C303KDGLCAUTO)
C107  ValueDisplayed: 0.03uF  [1812_254]  (hidden comment: C1812C303KDGLCAUTO)
C108  Cap_F: 100nF  VDC_V: 25V  [0603]  (hidden comment: 06033C104JAT2A)
D1  C6D20065G  [FP-C6D20065G_TO263-2-MFG]
D17  KG DELLS1.22-JGKH-24  [FP-KG DELLS1.22-JGKH-24_0603-MFG]  (value not drawn)
FB1  MH1608-601Y  [FP-MH1608-601Y_0603-MFG]
L1  value 160uH  [FP-B180974_PTH12_41MM5_40MM5-MFG]  (hidden comment: B180974)  (parts A,B of 2)
L2  SDEM20161T-4R7MS  [FP-SDEM20161T-4R7MS_SMD2-MFG]  (value not drawn)
L6  ValueDisplayed: 22µH  [SRP2313AA]  (hidden comment: SRP2313AA-220M)
R1  ValueDisplayed: 56  [0603]  (hidden comment: RG1608P-560-B-T5)
R6  ValueDisplayed: 20.0k  [0603]  (hidden comment: RC0603FR-0720KL)
R8  ValueDisplayed: 56  [0603]  (hidden comment: RG1608P-560-B-T5)
R9  Tolerance_%: 0.1%  ValueDisplayed: 10.0  [0603]  (hidden comment: RT0603BRD0710RL)
R10  Tolerance_%: 0.1%  ValueDisplayed: 10.0  [0603]  (hidden comment: RT0603BRD0710RL)
R17  value 3m  [FP-CSS2H-2512K-3L00F_2512-MFG]  (hidden comment: CSS2H-2512K-3L00F)
R105  ValueDisplayed: 5.6k  [0603]  (hidden comment: RC0603JR-075K6L)
R146  ValueDisplayed: 56  [0603]  (hidden comment: RG1608P-560-B-T5)
TP12  S2751-46R  [Harwin_S2751-46R]  (no BOM)
TP13  5001  [Keystone5001]
TP14  5001  [Keystone5001]
TP15  5001  [Keystone5001]
U1  LMG3522R030-Q1  [RQS0052C-C01-MFG]  (parts A,B of 2)
U3  INA181A2IDBV  [DBV0006A_N]

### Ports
Boost1_IN+ (in), Boost1_IN- (in), Boost_S1_Buff (in), CS_Boost1+ (out), CS_Boost1- (out), DC_Bus+ (out), DC_Bus- (out), PV1 Bus+ (out), PV1 Bus- (out), TEMP_Boost1_init (out), ~{FAULT}_Boost1_init (out), ~{OC}_Boost1_init (out)

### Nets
3V3_HVN: FB1.1
12V_HVN: C5.1(+) C6.1 U1.44(VDD)
GND_HVN: C17.2 C19.1 C108.1 R146.1 U3.2(GND) U3.5(REF)
GND_PV: C5.2(-) C6.2 C7.1 C8.1 C10.2 C12.1 C13.2 C100.2 C101.2 C106.2 C107.2 L2.1 R6.1 R9.1 R17.2 R105.1 TP13.1 U1.18(SOURCE) U1.19(SOURCE) U1.20(SOURCE) U1.21(SOURCE) U1.22(SOURCE) U1.23(SOURCE) U1.24(SOURCE) U1.25(SOURCE) U1.26(SOURCE) U1.28(SOURCE) U1.29(SOURCE) U1.30(SOURCE) U1.31(SOURCE) U1.32(SOURCE) U1.33(SOURCE) U1.34(SOURCE) U1.35(SOURCE) U1.36(SOURCE) U1.37(SOURCE) U1.38(SOURCE) U1.39(SOURCE) ; port DC_Bus-  [project net DC_Bus-]
Boost1_IN+: C30.2 L6.1 ; port Boost1_IN+
Boost1_IN-: C9.1 C30.1 R10.1 R17.1 ; port Boost1_IN-, port PV1 Bus-
Boost_S1_Buff: R1.1 ; port Boost_S1_Buff
CS_Boost1+: C19.2 R8.2 TP14.1 ; port CS_Boost1+
CS_Boost1-: R146.2 TP15.1 ; port CS_Boost1-
DC_Bus+: C10.1 C100.1 C101.1 C106.1 C107.1 D1.1(CATHODE) D1.3(CATHODE) ; port DC_Bus+
~{FAULT}_Boost1_init: U1.46(~{FAULT}) ; port ~{FAULT}_Boost1_init
~{OC}_Boost1_init: U1.48(~{OC}) ; port ~{OC}_Boost1_init
PV1 Bus+: C9.2 L1.5 L1.6 L6.2 ; port PV1 Bus+
TEMP_Boost1_init: U1.49(TEMP) ; port TEMP_Boost1_init
NetC7_2: C7.2 R1.2 U1.45(IN)
NetC8_2: C8.2 U1.51(LDO5V)
NetC12_2: C12.2 R6.2 U1.50(RDRV)
NetC13_1: C13.1 D17.1(CATHODE) U1.40(VNEG) U1.41(VNEG)
NetC17_1: C17.1 C108.2 FB1.2 U3.6(V+)
NetC18_1: C18.1 R9.2 U3.3(IN+)
NetC18_2: C18.2 R10.2 U3.4(IN-)
NetD1_2: D1.2(ANODE) L1.1 L1.2 TP12.1 U1.2(DRAIN) U1.3(DRAIN) U1.4(DRAIN) U1.5(DRAIN) U1.6(DRAIN) U1.7(DRAIN) U1.8(DRAIN) U1.9(DRAIN) U1.10(DRAIN) U1.11(DRAIN) U1.12(DRAIN) U1.13(DRAIN) U1.14(DRAIN) U1.15(DRAIN)
NetD17_2: D17.2(ANODE) R105.2
NetL2_2: L2.2 U1.42(BBSW)
NetR8_1: R8.1 U3.1(OUT)

Not connected (* = marked no-connect by the designer): L1 3(NC)* 4(NC)* 7(NC)* 8(NC)* 9(NC)* 10(NC)* 11(NC)* 12(NC)*; U1 1(1_NU)* 16(1_NU)* 17(2_NU)* 27(2_NU)* 43(2_NU)* 47(2_NU)* 52(2_NU)*

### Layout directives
net class HVN: 3V3_HVN, 12V_HVN, GND_HVN, GND_PV
net class Boost1SW: NetD1_2
net class HVP: DC_Bus+
net class Boost1p: PV1 Bus+

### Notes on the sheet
- Ceramic caps
- (near C10) film caps
- Vin= 2.7 to 5.5V
  VCM range= -0.2V to 26V
  Quiescent current= 300uA max
  BW= 210kHz
  Gain= 50V/V
- 3mOhm, 4W
- f3db = 796kHz
- Pshunt= 0.363W @520V, 11A
- (near R10) Current in unidirectionnal.
- current range= +-11A max with 3A riple.
- Max current that can be sensed: 22A (cc current PV = 18A)

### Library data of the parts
C5 = CMP-0081462-1: as C144 on sheet TIDA-010938 DCDC_Top
C6 = CMP-0750154-1: CAP, CERM, 10 µF, 25 V,+/- 10%, X7R, AEC-Q200 Grade 1, 1206; Manufacturer: Taiyo Yuden; AEC Qualified: Y; SizeZ_mm: 1.8; TaMax_C: 125°C; TaMin_C: -55°C; Cap_Case: 1206; Polarized: N; AEC Grade: 1; SizeY_mm: 1.6; Value: 10uF; SizeX_mm: 3.2; SizeAreaWB_mm2: 10.92; AEC Category: Q200; U/M: EA; SizeArea_mm2: 5.12
C7 C12 C19 = CMP-0007442-5: as C16 on sheet TIDA-010938 DCDC_Top
C8 C108 = CMP-0006752-5: CAP, CERM, 0.1 uF, 25 V, +/- 5%, X7R, 0603; Manufacturer: AVX; TaMin_C: -55°C; ESR_ohm: 0.05; Polarized: N; SizeAreaWB_mm2: 4.68; Value1: 0.05 ohm; U/M: EA; Value: 0.1uF; TaMax_C: 125°C; SizeZ_mm: 1; SizeX_mm: 1.6; SizeY_mm: 0.8; SizeArea_mm2: 1.28; AEC Category: Q200
C9 = CMP-0045101-1: 6 µF Film Capacitor 700V Polypropylene (PP), Metallized Radial; Manufacturer: KEMET; AEC Grade: Grade 2; AEC Qualified: Yes; Cap_F: 6µF; SizeZ_mm: 30.7mm; Tolerance_%: 5%; Value: 6µF
C10 = CMP-0045062-1: as C3 on sheet TIDA-010938 DCDC_Top
C13 = CMP-0007975-2: CAP, CERM, 2.2 uF, 25 V, +/- 10%, X7R, AEC-Q200 Grade 1, 0805; Manufacturer: TDK; TaMin_C: -55°C; Polarized: N; SizeAreaWB_mm2: 6.75; Value1: Unknown; U/M: EA; Value: 2.2uF; TaMax_C: 125°C; SizeZ_mm: 1.45; SizeX_mm: 2; SizeY_mm: 1.25; Cap_Case: 0805; SizeArea_mm2: 2.5; AEC Qualified: Y; AEC Grade: 1; AEC Category: Q200
C17 = CMP-0086152-1: CAP, CERM, 1 µF, 25 V,+/- 10%, X5R, 0603; Manufacturer: Taiyo Yuden; SizeAreaWB_mm2: 4.68; SizeZ_mm: 1; U/M: EA; Green_REACh: Passed; Value: 1uF; AEC Qualified: N; TaMax_C: 85°C; Green_Lifecycle: Active; AEC Category: Q200; SizeArea_mm2: 1.28; TaMin_C: -55°C; SizeY_mm: 0.8; SizeX_mm: 1.6
C18 = CMP-0079721-1: CAP, CERM, 0.01 µF, 25 V,+/- 10%, X7R, 0603; Manufacturer: Presidio Components; TaMin_C: -55°C; Polarized: N; SizeAreaWB_mm2: 4.68; U/M: EA; Value: 0.01uF; TaMax_C: 125°C; SizeZ_mm: 1; SizeX_mm: 1.6; SizeY_mm: 0.8; SizeArea_mm2: 1.28; AEC Category: Q200; ValueDisplayed: 0.01µF
C30 = CMP-0045188-1: as C2 on sheet TIDA-010938 DCDC_Top
C100 C101 C106 C107 = CMP-0009326-2: 0.03 µF ±10% 1000V (1kV) Ceramic Capacitor C0G, NP0 1812 (4532 Metric); Manufacturer: Kemet; Polarized: N; Value: 0.03uF; U/M: EA; Cap_F: 30nF; Value1: Unknown; TaMin_C: -55°C; TaMax_C: 125°C; Cap_Case: 1812; AEC Category: Q200; SizeArea_mm2: 14.4; SizeAreaWB_mm2: 23.1; SizeX_mm: 4.5; SizeY_mm: 3.2; SizeZ_mm: 2.54
D1 = CMP-0042032-1: Schottky Diode 650 V 20A Surface Mount TO-263-2; Manufacturer: Wolfspeed; AEC Qualified: No; SizeZ_mm: 4.82mm; TJmax_C: 175°C; Vf_V: 650V; Cap_F: 1153pF; Forward Current: 64A; Max Surge Forward Current: 135A; Peak Reverse Current: 5uA
D17 = CMP-0093310-1: as D14 on sheet TIDA-010938 DCDC_Top
FB1 = CMP-0037505-1: 600 Ohms @ 100 MHz 1 Power, Signal Line Ferrite Bead 0603 (1608 Metric) 1A 200mOhm; Manufacturer: Bourns; DCR_ohm: 0.2; SizeZ_mm: 1mm; AEC Qualified: No; Impedance At Frequency: 600Ω @ 100MHz; Test Frequency: 100MHz; Tolerance_%: 25%
L1 = CMP-0049239-1: Double Boost Inductor; Manufacturer: Bourns; Ind_H: 160µH; SizeZ_mm: 41.3mm; AEC Qualified: No; Test Frequency: 100kHz; Tolerance_%: 10%
L2 = CMP-0089347-1: 4.7µH Unshielded Inductor 1.1A 426mOhm Max 0806 (2016 Metric); Manufacturer: Cyntec; AEC Qualified: No; Material: Metal Dust; Isat: 1.26A; Test Frequency: 1MHz; DCR_ohm: 0.426; SizeZ_mm: 1mm; Tolerance_%: 20%
L6 = CMP-0081037-1: Inductor, Shielded, Metal Composite, 22 µH, 14 A, 0.011 ohm, AEC-Q200 Grade 0, SMD; Manufacturer: Bourns; Isat: 14A @ 30% inductance drop; Irms: 18A @ 40C rise; SizeAreaWB_mm2: 612; DCR_ohm: 0.011; Value: 22uH; Imax_A: 14A; SizeZ_mm: 13; SizeX_mm: 23.5; SizeY_mm: 22; SizeArea_mm2: 517; AEC Qualified: Y; AEC Grade: 0; AEC Category: Q200
R1 R8 R146 = CMP-0023572-3: as R144 on sheet TIDA-010938 DCDC_Top
R6 = CMP-0022906-5: RES, 20.0 k, 1%, 0.1 W, 0603; Manufacturer: Yageo; Power_W: 100mW; TempCo: 100 ppm/C; Value_Code: 20k0; Value: 20.0k; EIA_Code: E96; Res_ohm: 20k; SizeX_mm: 1.6; SizeY_mm: 0.8; SizeZ_mm: 1; Value2: 0.1W; SizeArea_mm2: 1.28; AEC Qualified: N; VDC_V: 75V; AEC Category: Q200; SizeAreaWB_mm2: 4.68
R9 R10 = CMP-0023661-3: RES, 10.0, 0.1%, 0.1 W, 0603; Manufacturer: Yageo America; Power_W: 100mW; TempCo: 25 ppm/C; Value_Code: 10R0; U/M: EA; Value: 10.0; EIA_Code: E192; Res_ohm: 10; SizeX_mm: 1.6; SizeY_mm: 0.8; SizeZ_mm: 1; Value2: 0.1W; SizeArea_mm2: 1.28; VDC_V: 75V; AEC Category: Q200
R17 = CMP-0043791-1: Res Metal Strip 2512 0.003 Ohm 1% 4W ±75ppm/C Pad SMD Automotive T/R; Manufacturer: Bourns; AEC Grade: Grade 0; AEC Qualified: Yes; SizeZ_mm: 0.81mm; TempCo: 75ppm/°C
R105 = CMP-0025933-5: RES, 5.6 k, 5%, 0.1 W, 0603; Manufacturer: Yageo; Power_W: 100mW; TempCo: 100 ppm/C; Value_Code: 5k60; Value: 5.6k; EIA_Code: E24; SizeX_mm: 1.6; SizeY_mm: 0.8; SizeZ_mm: 1; Value2: 0.1W; SizeArea_mm2: 1.28; AEC Qualified: N; VDC_V: 75V; AEC Category: Q200; SizeAreaWB_mm2: 4.68
TP12 = CMP-0003968-1: Test Point, SMT; Manufacturer: Harwin
TP13-TP15 = CMP-0055138-2: as TP34 on sheet TIDA-010938 DCDC_Top
U1 = CMP-0094891-1: 650-V 30-mΩ GaN FET with Integrated Driver, Protection, and Temperature Reporting; Manufacturer: Texas Instruments; Max Supply Voltage: 18V; TaMax_C: +125°C; TaMin_C: -40°C; Nominal Supply Current: 16mA; Number Of Outputs: 1; Standoff Height: 0mm; Min Supply Voltage: 7.5V; TJmax_C: +150°C; AEC Grade: Grade 1; SizeZ_mm: 1mm; Output Voltage: 520V; AEC Qualified: Yes
U3 = CMP-0013232-2: Bidirectional, Low- and High-Side Measurement, Multichannel, Voltage Output, Current-Sense Amplifier, DBV0006A (SOT-6); Manufacturer: Texas Instruments; SizeX_mm: 2.8; SizeY_mm: 2.9; CompType: IC; SizeZ_mm: 1.45; SizeArea_mm2: 8.12; SizeAreaWB_mm2: 14.82; U/M: EA

## Sheet TIDA-010938 DC-DC_Boost2.SchDoc
size 431 x 279 mm; Date: Not shown in title block; ApprovedBy: Not shown in title block; CheckedBy: Not shown in title block; Author: Not shown in title block; CompanyName: Not shown in title block; Engineer: Not shown in title block; Organization: Not shown in title block; Address1: Not shown in title block; Address2: Not shown in title block; Address3: Not shown in title block; Address4: Not shown in title block; DocumentNumber: 1; Revision: Use project parameter SCH_Rev; SheetNumber: 5; SheetTotal: 9; PageSetup: Record=PageOptions¦CenterHorizontal=True¦CenterVertical=True¦PrintScale=1.00¦XCorrection=1.00¦YCorrection=1.00¦PrintKind=0¦BorderSize=5000000¦LeftOffset=0¦BottomOffset=0¦Orientation=2¦PaperLength=1000¦PaperWidth=1000¦Scale=100¦PaperSource=15¦PrintQuality=600¦MediaType=1¦DitherType=10¦PaperKind=Letter¦PrintScaleMode=1
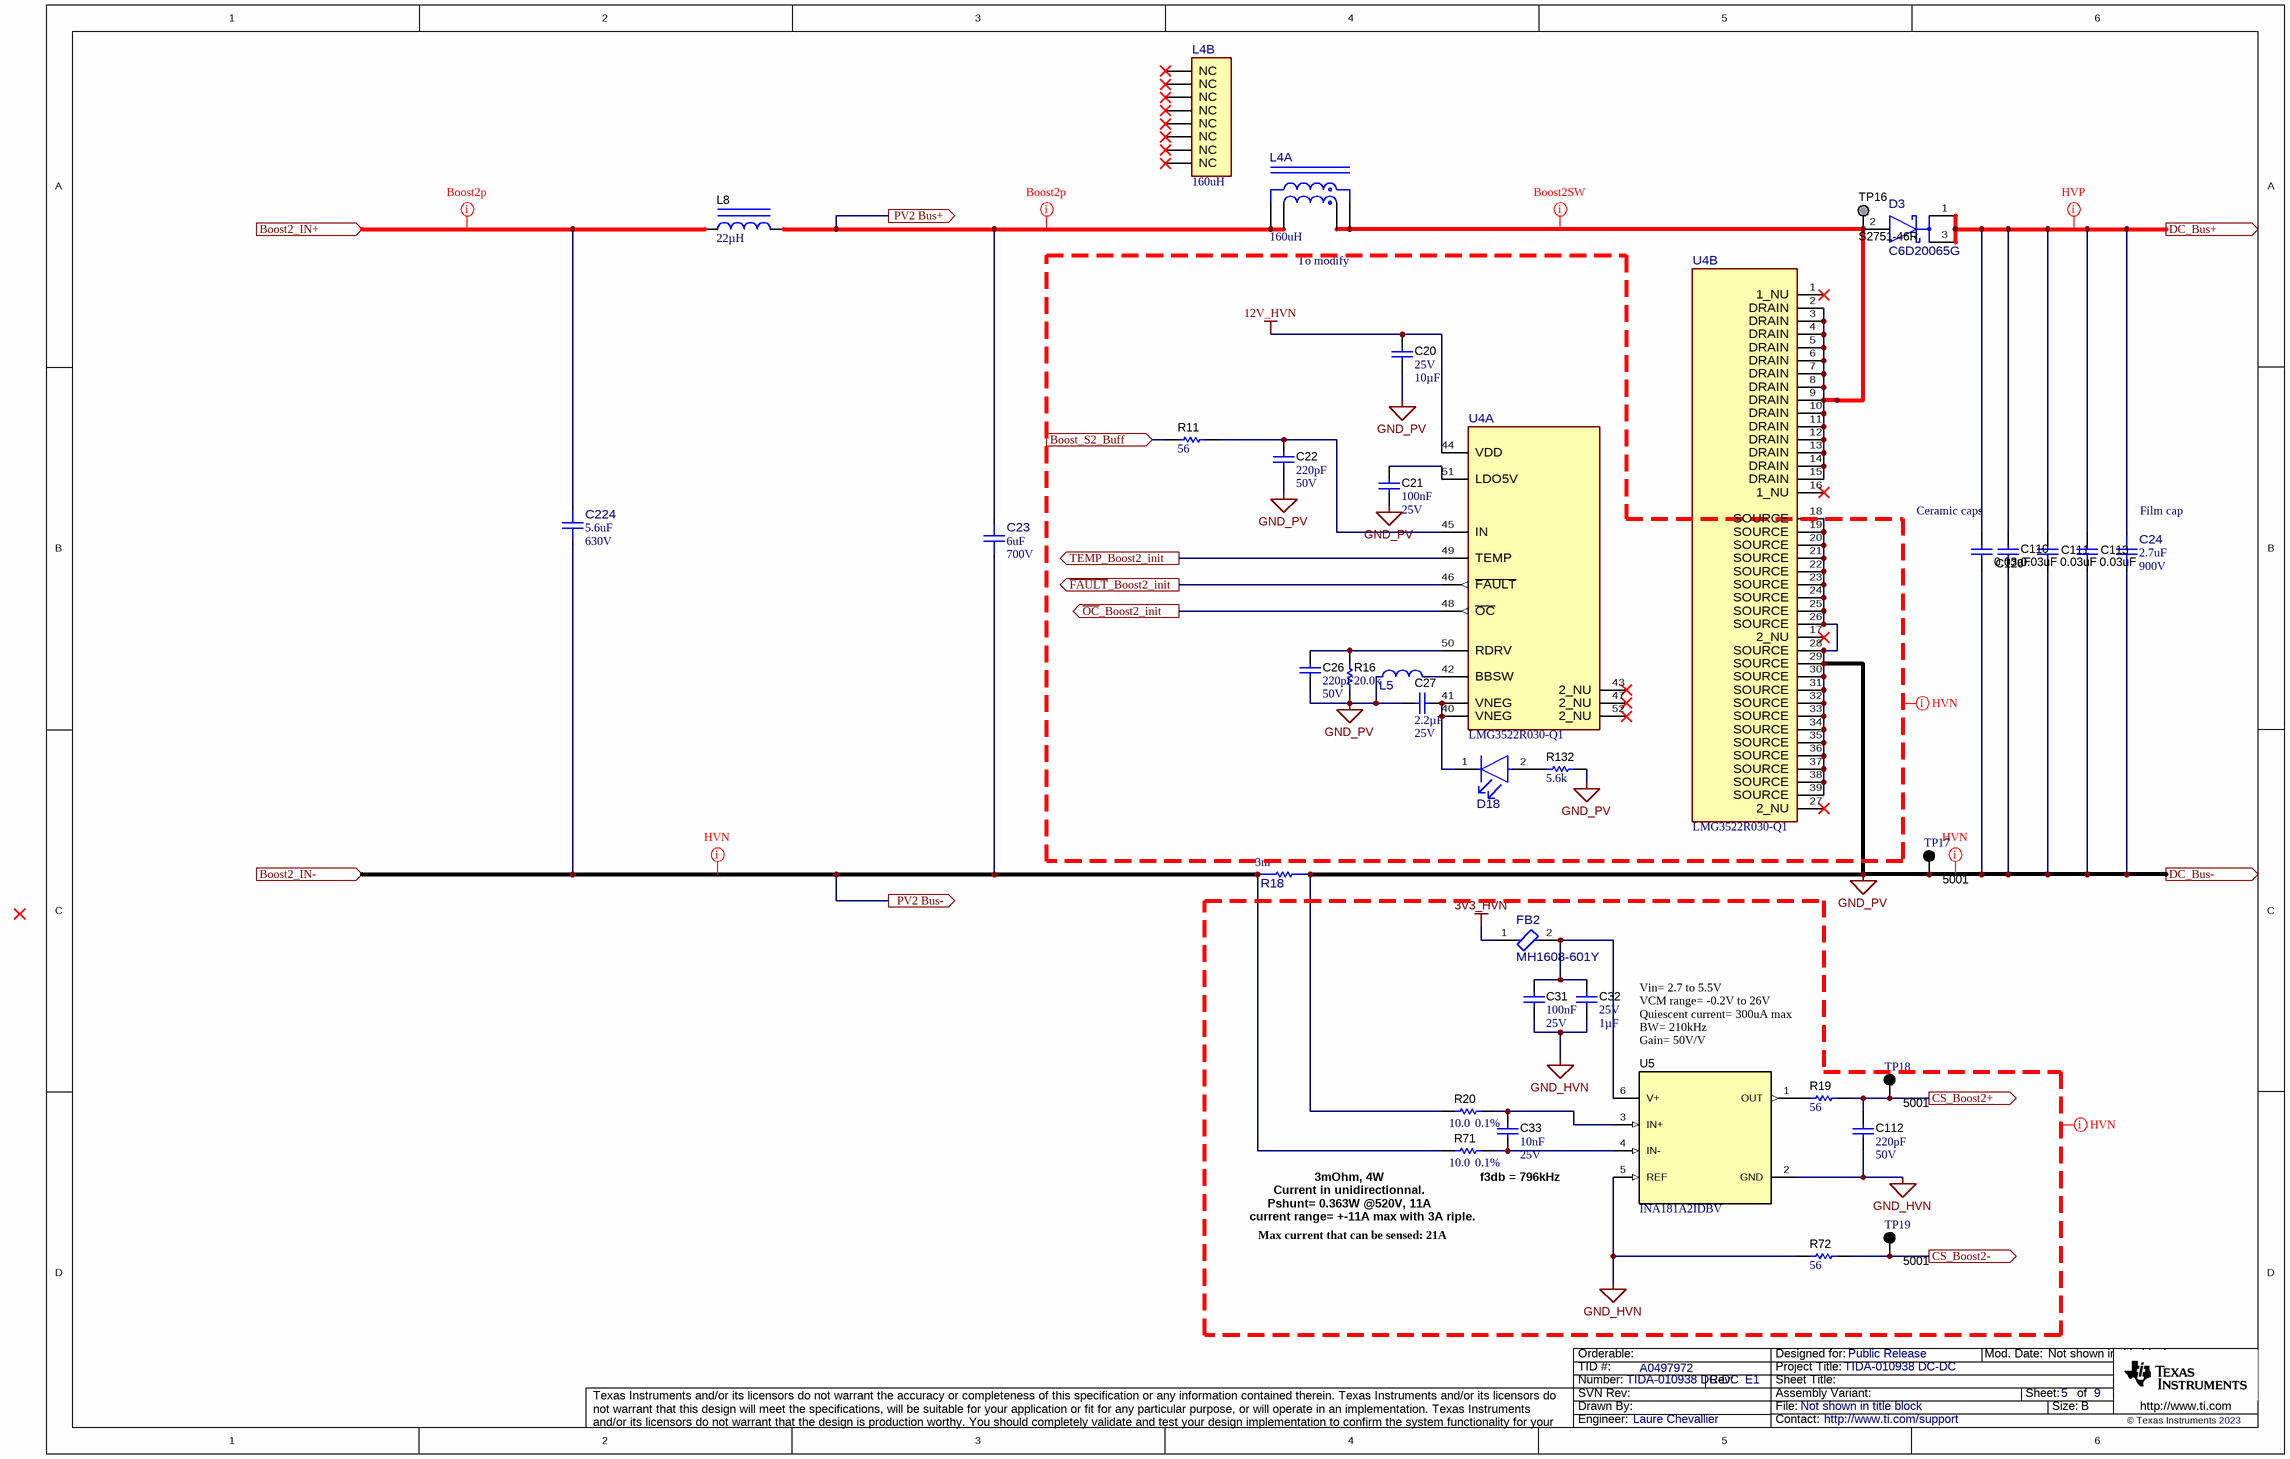
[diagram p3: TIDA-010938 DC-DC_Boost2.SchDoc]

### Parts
C20  VDC_V: 25V  ValueDisplayed: 10µF  [1206_180]  (hidden comment: TMK316AB7106KLHT)
C21  Cap_F: 100nF  VDC_V: 25V  [0603]  (hidden comment: 06033C104JAT2A)
C22  Cap_F: 220pF  VDC_V: 50V  [0603]  (hidden comment: GRM188R71H221KA01D)
C23  ValueDisplayed: 6uF  VDC_V: 700V  [FP-C4AUJBU4600M18J_RADIAL-MFG]  (hidden comment: C4AUJBU4600M18J)
C24  ValueDisplayed: 2.7uF  VDC_V: 900V  [FP-C4AKOBU4270A3YJ_RADIAL-MFG]  (hidden comment: C4AKOBU4270A3YJ)
C26  Cap_F: 220pF  VDC_V: 50V  [0603]  (hidden comment: GRM188R71H221KA01D)
C27  Cap_F: 2.2µF  VDC_V: 25V  [0805_HV]  (hidden comment: CGA4J3X7R1E225K125AB)
C31  Cap_F: 100nF  VDC_V: 25V  [0603]  (hidden comment: 06033C104JAT2A)
C32  VDC_V: 25V  ValueDisplayed: 1µF  [0603]  (hidden comment: TMK107BJ105KA-T)
C33  Cap_F: 10nF  VDC_V: 25V  [0603]  (hidden comment: SR0603X7R103K1NT95(F)#M123A)
C110  ValueDisplayed: 0.03uF  [1812_254]  (hidden comment: C1812C303KDGLCAUTO)
C111  ValueDisplayed: 0.03uF  [1812_254]  (hidden comment: C1812C303KDGLCAUTO)
C112  Cap_F: 220pF  VDC_V: 50V  [0603]  (hidden comment: GRM188R71H221KA01D)
C113  ValueDisplayed: 0.03uF  [1812_254]  (hidden comment: C1812C303KDGLCAUTO)
C126  ValueDisplayed: 0.03uF  [1812_254]  (hidden comment: C1812C303KDGLCAUTO)
C224  ValueDisplayed: 5.6uF  VDC_V: 630V  [FP-R533R456050P0M_RADIAL-MFG]  (hidden comment: R533R456050P0M)
D3  C6D20065G  [FP-C6D20065G_TO263-2-MFG]
D18  KG DELLS1.22-JGKH-24  [FP-KG DELLS1.22-JGKH-24_0603-MFG]  (value not drawn)
FB2  MH1608-601Y  [FP-MH1608-601Y_0603-MFG]
L4  value 160uH  [FP-B180974_PTH12_41MM5_40MM5-MFG]  (hidden comment: B180974)  (parts A,B of 2)
L5  SDEM20161T-4R7MS  [FP-SDEM20161T-4R7MS_SMD2-MFG]  (value not drawn)
L8  ValueDisplayed: 22µH  [SRP2313AA]  (hidden comment: SRP2313AA-220M)
R11  ValueDisplayed: 56  [0603]  (hidden comment: RG1608P-560-B-T5)
R16  ValueDisplayed: 20.0k  [0603]  (hidden comment: RC0603FR-0720KL)
R18  value 3m  [FP-CSS2H-2512K-3L00F_2512-MFG]  (hidden comment: CSS2H-2512K-3L00F)
R19  ValueDisplayed: 56  [0603]  (hidden comment: RG1608P-560-B-T5)
R20  Tolerance_%: 0.1%  ValueDisplayed: 10.0  [0603]  (hidden comment: RT0603BRD0710RL)
R71  Tolerance_%: 0.1%  ValueDisplayed: 10.0  [0603]  (hidden comment: RT0603BRD0710RL)
R72  ValueDisplayed: 56  [0603]  (hidden comment: RG1608P-560-B-T5)
R132  ValueDisplayed: 5.6k  [0603]  (hidden comment: RC0603JR-075K6L)
TP16  S2751-46R  [Harwin_S2751-46R]  (no BOM)
TP17  5001  [Keystone5001]
TP18  5001  [Keystone5001]
TP19  5001  [Keystone5001]
U4  LMG3522R030-Q1  [RQS0052C-C01-MFG]  (parts A,B of 2)
U5  INA181A2IDBV  [DBV0006A_N]

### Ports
Boost2_IN+ (in), Boost2_IN- (in), Boost_S2_Buff (in), CS_Boost2+ (out), CS_Boost2- (out), DC_Bus+ (out), DC_Bus- (out), PV2 Bus+ (out), PV2 Bus- (out), TEMP_Boost2_init (out), ~{FAULT}_Boost2_init (out), ~{OC}_Boost2_init (out)

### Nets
3V3_HVN: FB2.1
12V_HVN: C20.1 U4.44(VDD)
GND_HVN: C31.1 C32.2 C112.1 R72.1 U5.2(GND) U5.5(REF)
GND_PV: C20.2 C21.1 C22.1 C24.2 C26.1 C27.2 C110.2 C111.2 C113.2 C126.2 L5.1 R16.1 R18.2 R20.1 R132.1 TP17.1 U4.18(SOURCE) U4.19(SOURCE) U4.20(SOURCE) U4.21(SOURCE) U4.22(SOURCE) U4.23(SOURCE) U4.24(SOURCE) U4.25(SOURCE) U4.26(SOURCE) U4.28(SOURCE) U4.29(SOURCE) U4.30(SOURCE) U4.31(SOURCE) U4.32(SOURCE) U4.33(SOURCE) U4.34(SOURCE) U4.35(SOURCE) U4.36(SOURCE) U4.37(SOURCE) U4.38(SOURCE) U4.39(SOURCE) ; port DC_Bus-  [project net DC_Bus-]
Boost2_IN+: C224.2 L8.1 ; port Boost2_IN+
Boost2_IN-: C23.1 C224.1 R18.1 R71.1 ; port Boost2_IN-, port PV2 Bus-
Boost_S2_Buff: R11.1 ; port Boost_S2_Buff
CS_Boost2+: C112.2 R19.2 TP18.1 ; port CS_Boost2+
CS_Boost2-: R72.2 TP19.1 ; port CS_Boost2-
DC_Bus+: C24.1 C110.1 C111.1 C113.1 C126.1 D3.1(CATHODE) D3.3(CATHODE) ; port DC_Bus+
~{FAULT}_Boost2_init: U4.46(~{FAULT}) ; port ~{FAULT}_Boost2_init
~{OC}_Boost2_init: U4.48(~{OC}) ; port ~{OC}_Boost2_init
PV2 Bus+: C23.2 L4.5 L4.6 L8.2 ; port PV2 Bus+
TEMP_Boost2_init: U4.49(TEMP) ; port TEMP_Boost2_init
NetC21_2: C21.2 U4.51(LDO5V)
NetC22_2: C22.2 R11.2 U4.45(IN)
NetC26_2: C26.2 R16.2 U4.50(RDRV)
NetC27_1: C27.1 D18.1(CATHODE) U4.40(VNEG) U4.41(VNEG)
NetC31_2: C31.2 C32.1 FB2.2 U5.6(V+)
NetC33_1: C33.1 R20.2 U5.3(IN+)
NetC33_2: C33.2 R71.2 U5.4(IN-)
NetD3_2: D3.2(ANODE) L4.1 L4.2 TP16.1 U4.2(DRAIN) U4.3(DRAIN) U4.4(DRAIN) U4.5(DRAIN) U4.6(DRAIN) U4.7(DRAIN) U4.8(DRAIN) U4.9(DRAIN) U4.10(DRAIN) U4.11(DRAIN) U4.12(DRAIN) U4.13(DRAIN) U4.14(DRAIN) U4.15(DRAIN)
NetD18_2: D18.2(ANODE) R132.2
NetL5_2: L5.2 U4.42(BBSW)
NetR19_1: R19.1 U5.1(OUT)

Not connected (* = marked no-connect by the designer): L4 3(NC)* 4(NC)* 7(NC)* 8(NC)* 9(NC)* 10(NC)* 11(NC)* 12(NC)*; U4 1(1_NU)* 16(1_NU)* 17(2_NU)* 27(2_NU)* 43(2_NU)* 47(2_NU)* 52(2_NU)*

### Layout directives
net class HVN: 3V3_HVN, 12V_HVN, Boost2_IN-, DC_Bus-, GND_HVN, GND_PV
net class Boost2SW: NetD3_2
net class HVP: DC_Bus+
net class Boost2p: Boost2_IN+, PV2 Bus+

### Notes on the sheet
- To modify
- Ceramic caps
- (near C24) Film cap
- Vin= 2.7 to 5.5V
  VCM range= -0.2V to 26V
  Quiescent current= 300uA max
  BW= 210kHz
  Gain= 50V/V
- 3mOhm, 4W
- Pshunt= 0.363W @520V, 11A
- (near R71) Current in unidirectionnal.
- current range= +-11A max with 3A riple.
- f3db = 796kHz
- Max current that can be sensed: 21A (cc current PV = 18A)

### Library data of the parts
C20 = CMP-0750154-1: as C6 on sheet TIDA-010938 DC-DC_Boost1
C21 C31 = CMP-0006752-5: as C8 on sheet TIDA-010938 DC-DC_Boost1
C22 C26 C112 = CMP-0007442-5: as C16 on sheet TIDA-010938 DCDC_Top
C23 = CMP-0045101-1: as C9 on sheet TIDA-010938 DC-DC_Boost1
C24 = CMP-0045062-1: as C3 on sheet TIDA-010938 DCDC_Top
C27 = CMP-0007975-2: as C13 on sheet TIDA-010938 DC-DC_Boost1
C32 = CMP-0086152-1: as C17 on sheet TIDA-010938 DC-DC_Boost1
C33 = CMP-0079721-1: as C18 on sheet TIDA-010938 DC-DC_Boost1
C110 C111 C113 C126 = CMP-0009326-2: as C100 on sheet TIDA-010938 DC-DC_Boost1
C224 = CMP-0045188-1: as C2 on sheet TIDA-010938 DCDC_Top
D3 = CMP-0042032-1: as D1 on sheet TIDA-010938 DC-DC_Boost1
D18 = CMP-0093310-1: as D14 on sheet TIDA-010938 DCDC_Top
FB2 = CMP-0037505-1: as FB1 on sheet TIDA-010938 DC-DC_Boost1
L4 = CMP-0049239-1: as L1 on sheet TIDA-010938 DC-DC_Boost1
L5 = CMP-0089347-1: as L2 on sheet TIDA-010938 DC-DC_Boost1
L8 = CMP-0081037-1: as L6 on sheet TIDA-010938 DC-DC_Boost1
R11 R19 R72 = CMP-0023572-3: as R144 on sheet TIDA-010938 DCDC_Top
R16 = CMP-0022906-5: as R6 on sheet TIDA-010938 DC-DC_Boost1
R18 = CMP-0043791-1: as R17 on sheet TIDA-010938 DC-DC_Boost1
R20 R71 = CMP-0023661-3: as R9 on sheet TIDA-010938 DC-DC_Boost1
R132 = CMP-0025933-5: as R105 on sheet TIDA-010938 DC-DC_Boost1
TP16 = CMP-0003968-1: Test Point, SMT; Manufacturer: Harwin
TP17-TP19 = CMP-0055138-2: as TP34 on sheet TIDA-010938 DCDC_Top
U4 = CMP-0094891-1: as U1 on sheet TIDA-010938 DC-DC_Boost1
U5 = CMP-0013232-2: as U3 on sheet TIDA-010938 DC-DC_Boost1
